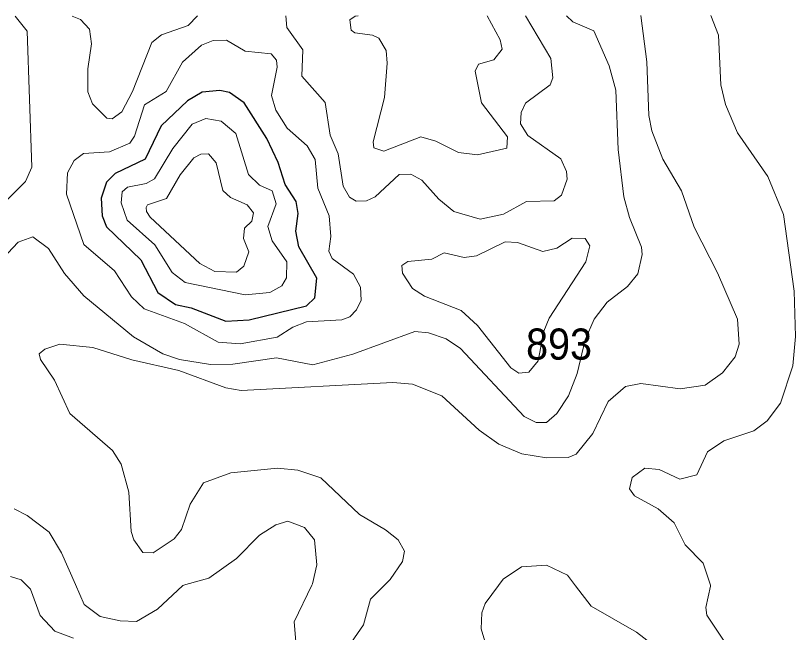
# Model space of a CAD drawing. Extents: x 473.9 to 500, y 7733.1 to 7760.8.
# Drawn here: x 482.693 to 484.699, y 7759.228 to 7760.813 of the extents above; entities that cross this region are included whole.
import ezdxf

# ---------------------------------------------------------------- set-up
doc = ezdxf.new("R2010")
doc.units = 0
doc.header["$LTSCALE"] = 0.032
doc.layers.add('1', color=7, linetype='Continuous', lineweight=25)
doc.layers.add('2', color=7, linetype='Continuous', lineweight=13)
doc.layers.add('21', color=7, linetype='Continuous')

msp = doc.modelspace()

# ---------------------------------------------------------------- linework, layer by layer
at = {"layer": '1'}
msp.add_lwpolyline([(483.4136, 7760.2589), (483.4201, 7760.3044), (483.4151, 7760.3353), (483.3865, 7760.3789), (483.3685, 7760.4355), (483.3393, 7760.4973), (483.2813, 7760.5895), (483.2431, 7760.6155), (483.2186, 7760.6208), (483.1729, 7760.6166), (483.1351, 7760.5945), (483.0679, 7760.5304), (483.0266, 7760.4447), (482.9496, 7760.4078), (482.9271, 7760.3855), (482.9131, 7760.3444), (482.9159, 7760.299), (482.9274, 7760.2708), (483.0156, 7760.1852), (483.0588, 7760.1016), (483.1047, 7760.0707), (483.1445, 7760.0619), (483.2337, 7760.0281), (483.2942, 7760.0317), (483.4414, 7760.0675), (483.4625, 7760.0877), (483.4679, 7760.1387), (483.4213, 7760.2191)], close=True, dxfattribs=at)
at = {"layer": '2'}
for points in [[(484.1103, 7760.813), (484.1262, 7760.7977), (484.1798, 7760.7738), (484.2199, 7760.6845), (484.2369, 7760.6217), (484.2427, 7760.4695), (484.2574, 7760.3478), (484.2719, 7760.2942), (484.3027, 7760.2185), (484.3044, 7760.1992), (484.2935, 7760.1494), (484.2667, 7760.1174), (484.2145, 7760.0767), (484.1807, 7760.0335), (484.1578, 7759.9802), (484.1373, 7759.8932), (484.1149, 7759.8364), (484.0849, 7759.7908), (484.0587, 7759.7675), (484.0318, 7759.7675), (484.0014, 7759.7831), (483.8376, 7759.9579), (483.8003, 7759.9829), (483.7547, 7759.9982), (483.7199, 7760.0015), (483.5603, 7759.9432), (483.4578, 7759.9162), (483.3645, 7759.9338), (483.2515, 7759.9171), (483.1941, 7759.917), (483.1148, 7759.9292), (483.0719, 7759.9437), (482.9968, 7759.9874), (482.8689, 7760.0934), (482.8193, 7760.1505), (482.7776, 7760.2146), (482.738, 7760.2447), (482.6998, 7760.2312), (482.6195, 7760.1465)], [(482.6553, 7760.3237), (482.7189, 7760.3873), (482.7351, 7760.4241), (482.7232, 7760.7732), (482.6919, 7760.8119)], [(483.557, 7759.2033), (483.5882, 7759.2478), (483.606, 7759.3137), (483.6417, 7759.3492), (483.6568, 7759.3643), (483.6878, 7759.4101), (483.6933, 7759.4369), (483.6766, 7759.4661), (483.6446, 7759.4919), (483.5776, 7759.5311), (483.4782, 7759.6253), (483.4187, 7759.645), (483.367, 7759.6499), (483.2466, 7759.6378), (483.1763, 7759.6125), (483.142, 7759.558), (483.1197, 7759.4927), (483.1008, 7759.4684), (483.0466, 7759.4324), (483.0201, 7759.4334), (482.997, 7759.4657), (482.9902, 7759.4871), (482.9842, 7759.5885), (482.9649, 7759.6605), (482.9428, 7759.696), (482.8326, 7759.7907), (482.7937, 7759.876), (482.7576, 7759.9291), (482.7543, 7759.944), (482.7686, 7759.956), (482.8071, 7759.9693), (482.8923, 7759.9603), (482.9925, 7759.9288), (483.1126, 7759.9008), (483.2338, 7759.8568), (483.2734, 7759.8495), (483.6637, 7759.8703), (483.714, 7759.8661), (483.789, 7759.8365), (483.8851, 7759.7475), (483.9355, 7759.712), (483.9949, 7759.6871), (484.0582, 7759.6766), (484.1145, 7759.6772), (484.1347, 7759.686), (484.1778, 7759.7389), (484.2174, 7759.8215), (484.2616, 7759.8602), (484.3013, 7759.8678), (484.4022, 7759.8542), (484.4664, 7759.8638), (484.511, 7759.8953), (484.5438, 7759.9366), (484.5536, 7759.9687), (484.5496, 7760.0335), (484.4985, 7760.152), (484.4384, 7760.2693), (484.4057, 7760.3632), (484.3573, 7760.4442), (484.3297, 7760.5171), (484.3214, 7760.5562), (484.3164, 7760.6944), (484.3013, 7760.8132)], [(482.8386, 7760.8121), (482.8605, 7760.8034), (482.8835, 7760.7785), (482.8884, 7760.7411), (482.879, 7760.6768), (482.8786, 7760.6173), (482.8912, 7760.5862), (482.9278, 7760.5499), (482.9412, 7760.5481), (482.9665, 7760.5657), (482.9936, 7760.6184), (483.0433, 7760.7441), (483.0685, 7760.7642), (483.1368, 7760.788), (483.1614, 7760.8123)], [(483.3884, 7760.8125), (483.3904, 7760.7828), (483.4315, 7760.7256), (483.4297, 7760.6576), (483.4892, 7760.5902), (483.5021, 7760.5063), (483.5227, 7760.4582), (483.5358, 7760.3749), (483.5518, 7760.3467), (483.5692, 7760.3366), (483.5955, 7760.337), (483.6177, 7760.3478), (483.6793, 7760.405), (483.7097, 7760.4059), (483.7376, 7760.3904), (483.7819, 7760.3415), (483.8201, 7760.3099), (483.8878, 7760.29), (483.9482, 7760.3031), (484.0066, 7760.3359), (484.0778, 7760.3371), (484.0974, 7760.3514), (484.1115, 7760.3926), (484.1103, 7760.4124), (484.0952, 7760.4452), (484.0106, 7760.505), (483.9918, 7760.5348), (483.9932, 7760.5644), (484.0047, 7760.5882), (484.0675, 7760.6355), (484.0745, 7760.6537), (484.0694, 7760.703), (484.0047, 7760.8129)], [(483.9058, 7760.8129), (483.9389, 7760.7514), (483.9442, 7760.7274), (483.9231, 7760.6996), (483.8833, 7760.6884), (483.8752, 7760.6707), (483.8914, 7760.5893), (483.9584, 7760.5014), (483.9565, 7760.4723), (483.8812, 7760.4556), (483.8325, 7760.4614), (483.7735, 7760.4908), (483.735, 7760.5014), (483.64, 7760.4651), (483.6148, 7760.4734), (483.6127, 7760.4888), (483.6419, 7760.6028), (483.6491, 7760.6907), (483.6459, 7760.7234), (483.6269, 7760.755), (483.611, 7760.7633), (483.566, 7760.7689), (483.5559, 7760.7762), (483.5526, 7760.8021), (483.5663, 7760.8115), (483.5738, 7760.8126)], [(484.4809, 7760.8133), (484.5007, 7760.7626), (484.5071, 7760.6355), (484.5186, 7760.5846), (484.5499, 7760.5122), (484.6278, 7760.3997), (484.6682, 7760.3025), (484.6951, 7760.1054), (484.6985, 7759.9885), (484.6919, 7759.913), (484.66, 7759.8171), (484.6257, 7759.7721), (484.592, 7759.7461), (484.5142, 7759.7205), (484.4727, 7759.6924), (484.4447, 7759.6327), (484.401, 7759.622), (484.3481, 7759.647), (484.3111, 7759.6498), (484.2789, 7759.6266), (484.2716, 7759.5974), (484.2849, 7759.5795), (484.3454, 7759.5455), (484.3864, 7759.5101), (484.4154, 7759.4535), (484.4609, 7759.4063), (484.4805, 7759.3491), (484.48, 7759.3467), (484.4685, 7759.2923), (484.4708, 7759.272), (484.5156, 7759.206)], [(482.6897, 7759.5453), (482.7227, 7759.5286), (482.7796, 7759.4857), (482.8115, 7759.4324), (482.8472, 7759.3516), (482.87, 7759.3001), (482.9111, 7759.269), (482.9625, 7759.2578), (483.0039, 7759.2563), (483.0578, 7759.2878), (483.1234, 7759.3485), (483.1314, 7759.3508), (483.1903, 7759.3677), (483.2612, 7759.418), (483.3208, 7759.4781), (483.3622, 7759.5042), (483.3935, 7759.514), (483.4365, 7759.4979), (483.4615, 7759.4664), (483.4682, 7759.4016), (483.4568, 7759.3529), (483.4553, 7759.3498), (483.4093, 7759.2555), (483.4183, 7759.153)], [(484.335, 7759.1933), (484.2899, 7759.2287), (484.173, 7759.2958), (484.1331, 7759.3478), (484.1121, 7759.3751), (484.0587, 7759.4008), (483.9943, 7759.3963), (483.947, 7759.365), (483.9346, 7759.3484), (483.9004, 7759.3025), (483.8918, 7759.2784), (483.8904, 7759.2376)], [(482.6801, 7759.3719), (482.7073, 7759.363), (482.7184, 7759.352), (482.7317, 7759.3389), (482.7563, 7759.2717), (482.7945, 7759.2309), (482.8419, 7759.2134)], [(483.8904, 7759.2376), (483.9072, 7759.1797)]]:
    msp.add_lwpolyline(points, dxfattribs=at)
for points in [[(483.5073, 7760.1888), (483.4989, 7760.2078), (483.5037, 7760.2453), (483.4996, 7760.2989), (483.4701, 7760.3702), (483.4634, 7760.4436), (483.4426, 7760.4788), (483.3917, 7760.5238), (483.3624, 7760.5706), (483.3517, 7760.6082), (483.3661, 7760.6806), (483.3642, 7760.6991), (483.3508, 7760.715), (483.2834, 7760.7217), (483.2359, 7760.7501), (483.201, 7760.7491), (483.171, 7760.7376), (483.1222, 7760.6939), (483.0807, 7760.6182), (483.0247, 7760.5836), (482.9988, 7760.5036), (482.9866, 7760.4854), (482.9346, 7760.4632), (482.8682, 7760.4592), (482.8439, 7760.441), (482.8265, 7760.4093), (482.8245, 7760.3541), (482.8684, 7760.2254), (482.9473, 7760.1573), (482.9916, 7760.0907), (483.0238, 7760.0595), (483.1277, 7760.0217), (483.2145, 7759.9736), (483.2707, 7759.9701), (483.3656, 7759.9867), (483.406, 7760.0128), (483.441, 7760.0263), (483.5323, 7760.031), (483.5531, 7760.039), (483.5702, 7760.0569), (483.5816, 7760.0818), (483.5804, 7760.1155), (483.5619, 7760.1489)], [(483.3529, 7760.2344), (483.3422, 7760.2716), (483.3635, 7760.3292), (483.3532, 7760.3632), (483.3205, 7760.3778), (483.2921, 7760.4049), (483.2598, 7760.5105), (483.2217, 7760.5424), (483.1827, 7760.5487), (483.1477, 7760.5343), (483.0976, 7760.4717), (483.0506, 7760.3942), (483.0288, 7760.3819), (482.9807, 7760.3722), (482.9677, 7760.3603), (482.9647, 7760.3325), (482.9805, 7760.2873), (483.0512, 7760.2245), (483.096, 7760.1532), (483.1296, 7760.127), (483.2836, 7760.0956), (483.347, 7760.1015), (483.3783, 7760.119), (483.3897, 7760.1391), (483.391, 7760.1807)], [(483.2793, 7760.2404), (483.2822, 7760.2667), (483.301, 7760.2847), (483.3047, 7760.3062), (483.2888, 7760.3267), (483.2458, 7760.3455), (483.2263, 7760.3637), (483.2088, 7760.4346), (483.1892, 7760.4581), (483.1699, 7760.4572), (483.1518, 7760.4479), (483.1165, 7760.4039), (483.0817, 7760.3434), (483.0328, 7760.3271), (483.0287, 7760.3203), (483.0299, 7760.3096), (483.0393, 7760.2952), (483.167, 7760.1759), (483.2059, 7760.1556), (483.2614, 7760.1542), (483.2804, 7760.1691), (483.2929, 7760.2059)], [(484.013, 7759.8973), (484.0367, 7759.9262), (484.0517, 7760.002), (484.0654, 7760.0361), (484.1593, 7760.1804), (484.1701, 7760.222), (484.158, 7760.2402), (484.1247, 7760.2409), (484.085, 7760.216), (484.0491, 7760.2073), (483.9836, 7760.2305), (483.952, 7760.2321), (483.8781, 7760.1957), (483.8465, 7760.192), (483.7957, 7760.2039), (483.7633, 7760.1872), (483.7023, 7760.1813), (483.6863, 7760.1708), (483.6883, 7760.1514), (483.7138, 7760.1116), (483.7446, 7760.0919), (483.8389, 7760.0552), (483.8814, 7760.0166), (483.9665, 7759.9077), (483.9874, 7759.8943)]]:
    msp.add_lwpolyline(points, close=True, dxfattribs=at)

# ---------------------------------------------------------------- texts
at = {"layer": '21', "width": 0.95}
msp.add_text('893', height=0.08, dxfattribs=at).set_placement((484.0059, 7759.9291))

doc.saveas('drawing.dxf')
